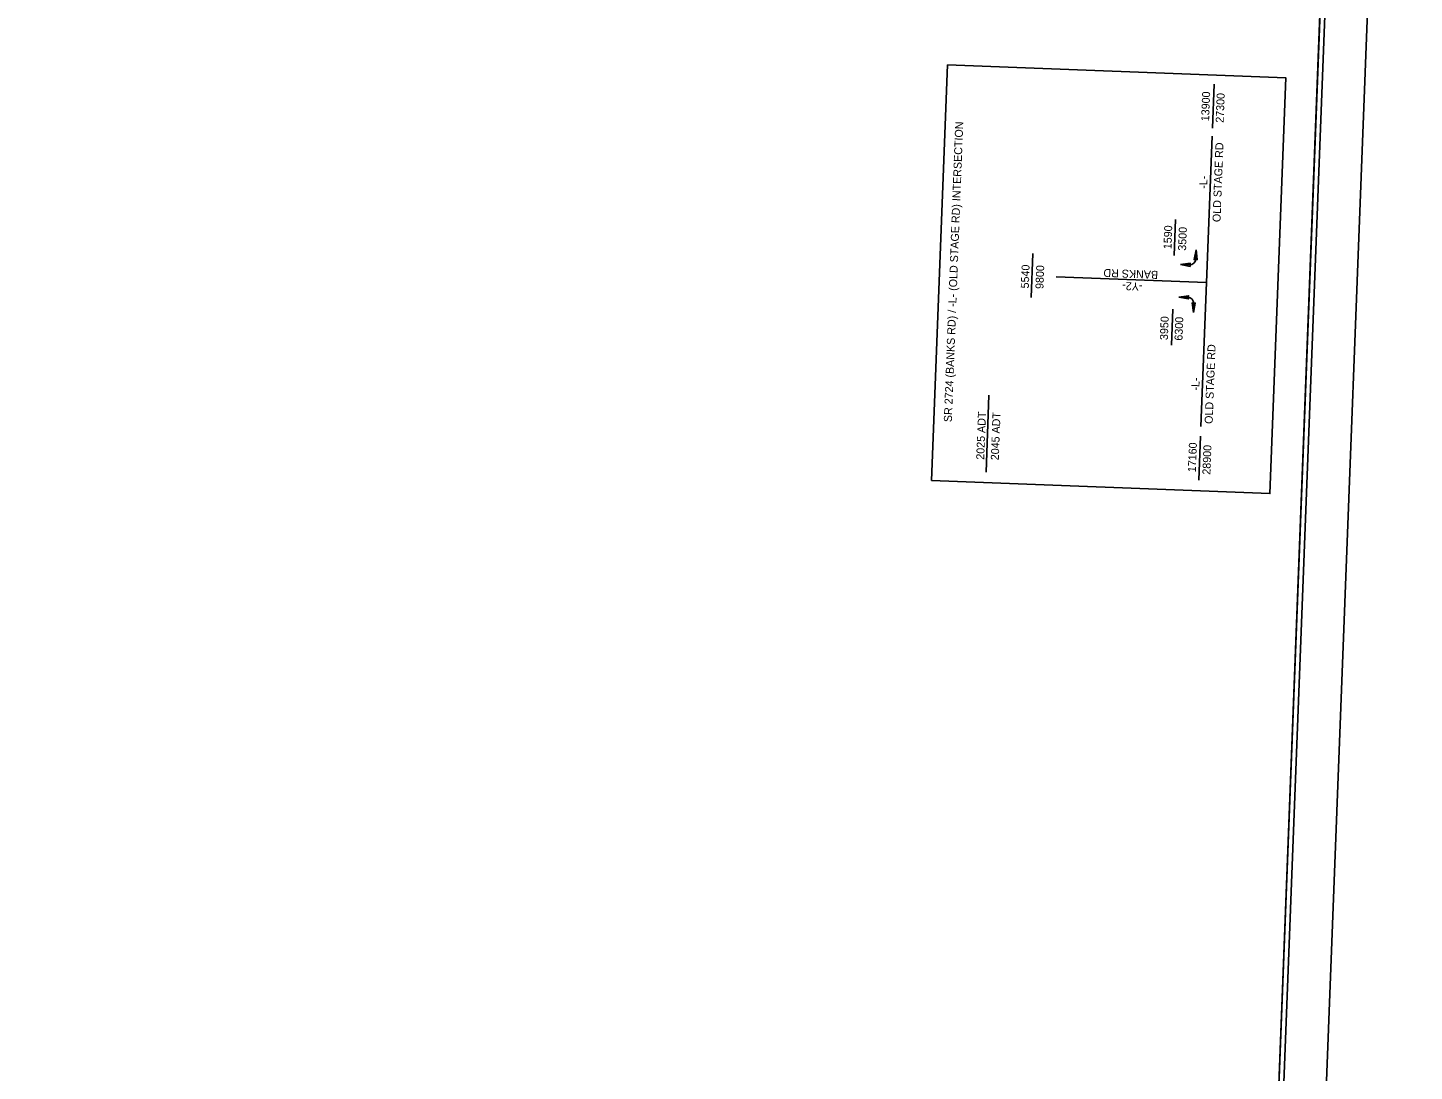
# Model space of a CAD drawing. Extents: x 2097096 to 2098260, y 686401 to 688363.
# Drawn here: x 2097529 to 2098260, y 686951 to 687502 of the extents above; entities that cross this region are included whole.
import ezdxf

# ---------------------------------------------------------------- set-up
doc = ezdxf.new("R2010")
doc.units = 0
for name, color, linetype in [('Prop PHM Legend CELL', 7, 'Continuous'), ('Prop PHM Text', 7, 'Continuous'), ('Sheet Layout Plan Border', 7, 'Continuous'), ('Sheet Plot Border Inside CELL', 7, 'Continuous'), ('Sheet Plot Border Outside CELL', 7, 'Continuous'), ('Sheet Profile CELL', 7, 'Continuous')]:
    doc.layers.add(name, color=color, linetype=linetype)

msp = doc.modelspace()

# ---------------------------------------------------------------- linework, layer by layer
at = {"layer": 'Prop PHM Legend CELL'}
msp.add_lwpolyline([(2098005.32, 687262.8), (2098013.73, 687482.01), (2098192.02, 687475.17), (2098183.61, 687255.96)], close=True, dxfattribs=at)
at = {"layer": 'Prop PHM Text'}
for p, q in [((2098153.28, 687448.63), (2098154.16, 687471.87)), ((2098150.16, 687367.25), (2098153.12, 687444.36)), ((2098133.21, 687381.59), (2098133.93, 687400.58)), ((2098057.83, 687359.33), (2098058.71, 687382.57)), ((2098144.68, 687384.42), (2098144.5, 687379.61)), ((2098136.49, 687376.82), (2098141.31, 687376.65)), ((2098070.98, 687370.29), (2098150.16, 687367.25)), ((2098150.16, 687367.25), (2098147.25, 687291.37)), ((2098135.67, 687359.62), (2098140.48, 687359.44)), ((2098131.7, 687334.17), (2098132.43, 687353.16)), ((2098143.26, 687351.43), (2098143.44, 687356.24)), ((2098034.02, 687267.23), (2098035.56, 687307.91)), ((2098146.13, 687263.05), (2098147.01, 687286.3))]:
    msp.add_line(p, q, dxfattribs=at)
for points in [[(2098144.68, 687384.42), (2098143.65, 687379.4), (2098145.34, 687379.33)], [(2098136.49, 687376.82), (2098141.51, 687375.79), (2098141.58, 687377.48)], [(2098135.67, 687359.62), (2098140.69, 687358.59), (2098140.75, 687360.27)], [(2098143.26, 687351.43), (2098144.29, 687356.45), (2098142.61, 687356.52)]]:
    msp.add_lwpolyline(points, close=True, dxfattribs=at)
for centre, start, end in [((2098141.42, 687379.72), 267.82254, 357.81893), ((2098140.36, 687356.36), 357.82254, 87.81893)]:
    msp.add_arc(centre, 3.08, start, end, dxfattribs=at)
at = {"layer": 'Sheet Layout Plan Border'}
msp.add_lwpolyline([(2098179.19, 686705.44), (2097129.59, 686735.95), (2097177.17, 687976.48), (2097364.33, 687969.3), (2097368.7, 688083.22), (2098230.76, 688050.16)], close=True, dxfattribs=at)
at = {"layer": 'Sheet Plot Border Inside CELL'}
msp.add_lwpolyline([(2098173.22, 686483.26), (2098237.09, 688148.54), (2097182.76, 688188.97), (2097118.9, 686523.7)], close=True, dxfattribs=at)
at = {"layer": 'Sheet Plot Border Outside CELL'}
msp.add_lwpolyline([(2098195.16, 686469.41), (2098259.69, 688152.17), (2097160.5, 688194.33), (2097095.97, 686511.57)], close=True, dxfattribs=at)
at = {"layer": 'Sheet Profile CELL'}
msp.add_line((2098176.58, 686637.25), (2098234.06, 688136.14), dxfattribs=at)
msp.add_lwpolyline([(2097184.83, 688176.38), (2097127.35, 686677.48), (2098176.58, 686637.25), (2098234.06, 688136.14)], close=True, dxfattribs=at)

# ---------------------------------------------------------------- texts
at = {"layer": 'Prop PHM Text'}
for s, height, rotation, p in [('13900', 4.219, 87.8037, (2098151.54, 687452.24)), ('27300', 4.219, 87.8037, (2098159.22, 687451.44)), ('SR 2724 (BANKS RD) / -L- (OLD STAGE RD) INTERSECTION', 4.2188, 87.8037, (2098015.95, 687293.58)), ('OLD STAGE RD', 4.2188, 87.83056, (2098157.56, 687399.06)), ('-L-', 4.219, 87.83056, (2098150.51, 687416.63)), ('1590', 4.219, 87.85747, (2098131.71, 687384.77)), ('3500', 4.219, 87.85747, (2098139.39, 687383.98)), ('5540', 4.219, 87.8037, (2098056.52, 687364.09)), ('9800', 4.219, 87.8037, (2098064.22, 687363.8)), ('BANKS RD', 4.219, 177.83056, (2098124.75, 687373.37)), ('-Y2- ', 4.219, 177.83056, (2098116.52, 687367.13)), ('3950', 4.219, 87.83059, (2098129.81, 687336.86)), ('6300', 4.219, 87.83059, (2098137.51, 687336.57)), ('OLD STAGE RD', 4.2188, 87.83056, (2098153.41, 687292.65)), ('-L-', 4.219, 87.83056, (2098146.36, 687310.23)), ('2025 ADT', 4.219, 87.8037, (2098033.01, 687273.77)), ('2045 ADT', 4.219, 87.8037, (2098040.71, 687273.47)), ('17160', 4.219, 87.8037, (2098144.56, 687267.17)), ('28900', 4.219, 87.8037, (2098152.22, 687265.86))]:
    msp.add_text(s, height=height, rotation=rotation, dxfattribs=at).set_placement(p)

doc.saveas('drawing.dxf')
